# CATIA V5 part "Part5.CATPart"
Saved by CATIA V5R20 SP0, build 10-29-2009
Part number: Part5
Bounding box of the stored display mesh (mm): x 206.4 to 244.5, y 17.599 to 55.311, z 12.7 to 88.9
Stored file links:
  C:\Users\TAK SYS\Desktop\Part5.CATPart
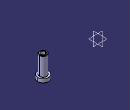
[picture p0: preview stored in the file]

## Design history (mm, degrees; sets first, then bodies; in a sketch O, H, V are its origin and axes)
Body1 (main body)
  DatumSurface1
  Sketch1 on face of DatumSurface1, origin (0, 0, 12.7), H (1, 0, 0), V (0, 1, 0)
    circle A1 centre (225.4496, 36.4549) radius 19.05
    circle A2 centre (225.4496, 36.4549) radius 12.7
    circle A3 centre (225.4496, 36.4549) radius 8.001
    radius A1 = 19.05
    radius A2 = 12.7
    radius A3 = 8.001
  Pad1: profile Sketch1.A1, length 12.7
  Pad2: profile Sketch1.A3, length 76.2
  Chamfer1: length 1.524, angle 45, on edge [face of Pad2 from Sketch1.A2 | end face of Pad2]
